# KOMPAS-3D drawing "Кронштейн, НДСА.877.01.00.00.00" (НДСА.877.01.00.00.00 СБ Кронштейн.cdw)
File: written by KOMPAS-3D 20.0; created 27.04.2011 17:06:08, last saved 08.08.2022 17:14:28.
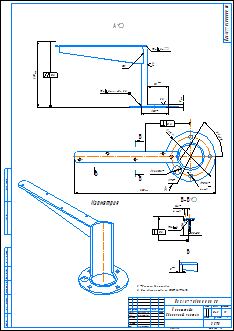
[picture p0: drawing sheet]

Sheet 1: A2, portrait

Document properties: Автор: Мочегов И.Н.; Организация: ЭСТО-Вакуум; Масса: 0.40703; 256478034055: <item xmlns="http://appius.ru/pdm" xmlns:xs="http://www.w3.org/2001/XMLSchema" xmlns:xsi="http://www.w3.org/2001/XMLSchema-instance" xsi:type="item">  <element xmlns:d2p1="http://v8.1c.ru/8.1/data/enterprise/current-config" xsi:type="d2p1:CatalogRef.aps_Элемен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; 256478036255: <item xmlns="http://appius.ru/pdm" xmlns:xs="http://www.w3.org/2001/XMLSchema" xmlns:xsi="http://www.w3.org/2001/XMLSchema-instance" xsi:type="item">  <element xmlns:d2p1="http://v8.1c.ru/8.1/data/enterprise/current-config" xsi:type="d2p1:CatalogRef.aps_Элемен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; PDM_DOCXDTO: <item xmlns="http://appius.ru/pdm" xmlns:xs="http://www.w3.org/2001/XMLSchema" xmlns:xsi="http://www.w3.org/2001/XMLSchema-instance" xsi:type="item">  <element xmlns:d2p1="http://v8.1c.ru/8.1/data/enterprise/current-config" xsi:type="d2p1:CatalogRef.aps_Элемен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; PDM_ITEMXDTO: <item xmlns="http://appius.ru/pdm" xmlns:xs="http://www.w3.org/2001/XMLSchema" xmlns:xsi="http://www.w3.org/2001/XMLSchema-instance" xsi:type="item">  <element xmlns:d2p1="http://v8.1c.ru/8.1/data/enterprise/current-config" xsi:type="d2p1:CatalogRef.aps_Элемен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; PLM_CDWXDTO: <item xmlns="http://appius.ru/pdm" xmlns:xs="http://www.w3.org/2001/XMLSchema" xmlns:xsi="http://www.w3.org/2001/XMLSchema-instance" xsi:type="item">  <element xmlns:d2p1="http://v8.1c.ru/8.1/data/enterprise/current-config" xsi:type="d2p1:CatalogRef.aps_Элемен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; Полное имя файла: ..\..\PLM\НДСА.877.01.00.00.00 Кронштейн.a3d; PDM_DOCXDTO: <item xmlns="http://appius.ru/pdm" xmlns:xs="http://www.w3.org/2001/XMLSchema" xmlns:xsi="http://www.w3.org/2001/XMLSchema-instance" xsi:type="item">  <element xmlns:d2p1="http://v8.1c.ru/8.1/data/enterprise/current-config" xsi:type="d2p1:CatalogRef.aps_Элемен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; PDM_ITEMXDTO: <item xmlns="http://appius.ru/pdm" xmlns:xs="http://www.w3.org/2001/XMLSchema" xmlns:xsi="http://www.w3.org/2001/XMLSchema-instance" xsi:type="item">  <element xmlns:d2p1="http://v8.1c.ru/8.1/data/enterprise/current-config" xsi:type="d2p1:CatalogRef.aps_Элемен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

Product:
- Part/product: Кронштейн  | designation НДСА.877.01.00.00.00
    Масса: 0.40703
    Раздел спецификации: Сборочные единицы
    Форматы листов документа: A2
    additional columns: <item xmlns="http://appius.ru/pdm" xmlns:xs="http://www.w3.org/2001/XMLSchema" x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; <item xmlns="http://appius.ru/pdm" xmlns:xs="http://www.w3.org/2001/XMLSchema" x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; <item xmlns="http://appius.ru/pdm" xmlns:xs="http://www.w3.org/2001/XMLSchema" x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; <item xmlns="http://appius.ru/pdm" xmlns:xs="http://www.w3.org/2001/XMLSchema" x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
    source file: НДСА.877.01.00.00.00 СБ Кронштейн.cdw
  - Component [detail]: Планка  | designation НДСА.876.01.00.00.04  | pos. 4
      Материал: Лист$d3,00 ГОСТ 19904-90;12Х18Н10Т ГОСТ 5582-75$ (density 7900 kg/m3)
      Масса: 0.086824
      Раздел спецификации: Детали
      Форматы листов документа: A4
      additional columns: <item xmlns="http://appius.ru/pdm" xmlns:xs="http://www.w3.org/2001/XMLSchema" x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; <item xmlns="http://appius.ru/pdm" xmlns:xs="http://www.w3.org/2001/XMLSchema" x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; <item xmlns="http://appius.ru/pdm" xmlns:xs="http://www.w3.org/2001/XMLSchema" x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; <item xmlns="http://appius.ru/pdm" xmlns:xs="http://www.w3.org/2001/XMLSchema" x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; <item xmlns="http://appius.ru/pdm" xmlns:xs="http://www.w3.org/2001/XMLSchema" x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; <item xmlns="http://appius.ru/pdm" xmlns:xs="http://www.w3.org/2001/XMLSchema" x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; <item xmlns="http://appius.ru/pdm" xmlns:xs="http://www.w3.org/2001/XMLSchema" x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; <item xmlns="http://appius.ru/pdm" xmlns:xs="http://www.w3.org/2001/XMLSchema" x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
      source file: ..\..\PLM\НДСА.876.01.00.00.04 Планка.cdw, ..\..\PLM\НДСА.876.01.00.00.04 Планка.m3d
  - Component [detail]: Ребро  | designation НДСА.876.01.00.00.03  | pos. 2
      Материал: Лист $b3 ГОСТ 19903-74;12Х18Н10Т ГОСТ 7350-77$ (density 7900 kg/m3)
      Масса: 0.0885788
      Раздел спецификации: Детали
      Форматы листов документа: A4
      additional columns: <item xmlns="http://appius.ru/pdm" xmlns:xs="http://www.w3.org/2001/XMLSchema" x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; <item xmlns="http://appius.ru/pdm" xmlns:xs="http://www.w3.org/2001/XMLSchema" x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; <item xmlns="http://appius.ru/pdm" xmlns:xs="http://www.w3.org/2001/XMLSchema" x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; <item xmlns="http://appius.ru/pdm" xmlns:xs="http://www.w3.org/2001/XMLSchema" x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; <item xmlns="http://appius.ru/pdm" xmlns:xs="http://www.w3.org/2001/XMLSchema" x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; <item xmlns="http://appius.ru/pdm" xmlns:xs="http://www.w3.org/2001/XMLSchema" x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; <item xmlns="http://appius.ru/pdm" xmlns:xs="http://www.w3.org/2001/XMLSchema" x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; <item xmlns="http://appius.ru/pdm" xmlns:xs="http://www.w3.org/2001/XMLSchema" x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
      source file: ..\..\PLM\НДСА.876.01.00.00.03 Ребро.cdw, ..\..\PLM\НДСА.876.01.00.00.03 Ребро.m3d
  - Component [detail]: Труба  | designation НДСА.877.01.00.00.01  | pos. 1
      Материал: Труба  50х3-12Х18Н10Т ГОСТ 9941-81 (density 7900 kg/m3)
      Масса: 0.135922
      Раздел спецификации: Детали
      Форматы листов документа: A4
      additional columns: <item xmlns="http://appius.ru/pdm" xmlns:xs="http://www.w3.org/2001/XMLSchema" x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; <item xmlns="http://appius.ru/pdm" xmlns:xs="http://www.w3.org/2001/XMLSchema" x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; <item xmlns="http://appius.ru/pdm" xmlns:xs="http://www.w3.org/2001/XMLSchema" x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; <item xmlns="http://appius.ru/pdm" xmlns:xs="http://www.w3.org/2001/XMLSchema" x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; <item xmlns="http://appius.ru/pdm" xmlns:xs="http://www.w3.org/2001/XMLSchema" x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; <item xmlns="http://appius.ru/pdm" xmlns:xs="http://www.w3.org/2001/XMLSchema" x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; <item xmlns="http://appius.ru/pdm" xmlns:xs="http://www.w3.org/2001/XMLSchema" x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
      source file: ..\..\PLM\НДСА.877.01.00.00.01 Труба.m3d, НДСА.877.01.00.00.01 Труба.cdw
  - Component [detail]: Кольцо  | designation НДСА.876.01.00.00.01  | pos. 3
      Материал: Лист $b3 ГОСТ 19903-74;12Х18Н10Т ГОСТ 7350-77$ (density 7900 kg/m3)
      Масса: 0.0957047
      Раздел спецификации: Детали
      Форматы листов документа: A4
      additional columns: <item xmlns="http://appius.ru/pdm" xmlns:xs="http://www.w3.org/2001/XMLSchema" x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; <item xmlns="http://appius.ru/pdm" xmlns:xs="http://www.w3.org/2001/XMLSchema" x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; <item xmlns="http://appius.ru/pdm" xmlns:xs="http://www.w3.org/2001/XMLSchema" x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; <item xmlns="http://appius.ru/pdm" xmlns:xs="http://www.w3.org/2001/XMLSchema" x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; <item xmlns="http://appius.ru/pdm" xmlns:xs="http://www.w3.org/2001/XMLSchema" x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; <item xmlns="http://appius.ru/pdm" xmlns:xs="http://www.w3.org/2001/XMLSchema" x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; <item xmlns="http://appius.ru/pdm" xmlns:xs="http://www.w3.org/2001/XMLSchema" x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; <item xmlns="http://appius.ru/pdm" xmlns:xs="http://www.w3.org/2001/XMLSchema" x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
      source file: ..\..\PLM\НДСА.876.01.00.00.01 Кольцо.cdw, ..\..\PLM\НДСА.876.01.00.00.01 Кольцо.m3d

Title block, sheet 1: Наименование: Кронштейн / Сборочный чертеж; Масса: 0,41; scale: 1:1; Количество листов документа: 1; organisation: ЭСТО; Форматы листов документа: A2; stored path: C:\_Мочегов\Приказ №2-11 Разработка нагревателей\Накальный (Гор) УКРД.772.05-01\_В PDM\УКРД.772.08.02.00.00 СБ Кронштейн.cdw; Разработал: Щербакова А.В.; Проверил: Горностаев П.А.; Утвердил: Белецкий В.Е.; Разработал, date: 08.08.2022

Views: Проекционный вид 3, Разрез Б-Б, Вид по стрелке 7
Referenced files in C:\Users\cherbakova\Desktop\PLM\: НДСА.877.01.00.00.00 Кронштейн.a3d, НДСА.876.01.00.00.04 Планка.m3d, НДСА.876.01.00.00.03 Ребро.m3d, НДСА.876.01.00.00.01 Кольцо.m3d, НДСА.877.01.00.00.01 Труба.m3d
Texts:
  НДСА.877.01.00.00.00
  Кольцо
  НДСА.876.01.00.00.01
  НДСА.876.01.00.00.01 Кольцо
  Труба
  НДСА.877.01.00.00.01
  НДСА.877.01.00.00.01 Труба
  Ребро
  НДСА.876.01.00.00.03
  НДСА.876.01.00.00.03 Ребро
  Планка
  НДСА.876.01.00.00.04
  НДСА.876.01.00.00.04 Планка
  НДСА.877.01.00.00.00 Кронштейн
Dimensions and other numbers on the sheet: 255; 90; 0,2; 70; 7; 4 отв.; 16,2; 4; 2№1; 8,5±0,5; 5; 1; 1:1; 0,41; 08.08.2022

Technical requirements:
  *Размеры для справок
  Все сварные швы по ГОСТ 14771-76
